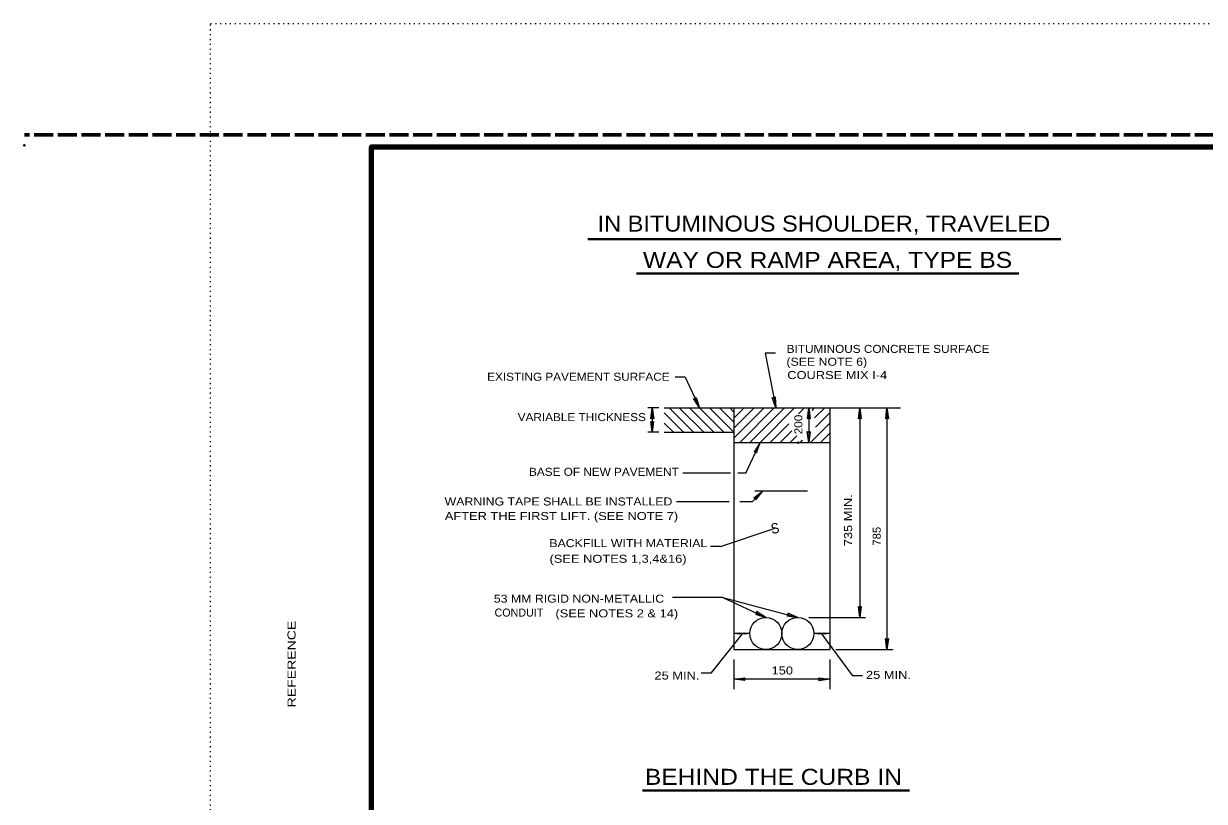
# Model space of a CAD drawing. Extents: x 312583 to 312854, y 144419 to 144597.
# Drawn here: x 312583.5 to 312695.6, y 144522.9 to 144596.8 of the extents above; entities that cross this region are included whole.
import ezdxf
from ezdxf.enums import TextEntityAlignment as Align

# ---------------------------------------------------------------- set-up
doc = ezdxf.new("R2010")
doc.units = 0
doc.header["$LTSCALE"] = 0.3
doc.header["$PDMODE"] = 32
doc.header["$PDSIZE"] = 0.15
doc.linetypes.add('DOTTED', pattern=[1.5, 0.3, -1.2])
doc.linetypes.add('LONG_DASHED', pattern=[7.5, 6, -1.5])
for name, color, linetype, lineweight in [('1', 7, 'Continuous', 13), ('62', 7, 'DOTTED', 13), ('63', 7, 'LONG_DASHED', 60)]:
    doc.layers.add(name, color=color, linetype=linetype, lineweight=lineweight)

msp = doc.modelspace()

# ---------------------------------------------------------------- linework, layer by layer
at = {"layer": '1', "lineweight": 40}
for p, q in [((312637.0349, 144576.3049), (312681.9618, 144576.3049)), ((312641.6591, 144573.0677), (312677.9712, 144573.0677)), ((312642.2278, 144523.9644), (312667.5907, 144523.9644))]:
    msp.add_line(p, q, dxfattribs=at)
at = {"layer": '1'}
for p, q in [((312646.2857, 144563.1996), (312645.335, 144563.1996)), ((312646.2857, 144563.1996), (312647.6427, 144560.2939)), ((312643.771, 144560.2939), (312642.7514, 144560.2939)), ((312643.1577, 144560.2939), (312643.1577, 144557.9786)), ((312646.1247, 144557.9786), (312644.2847, 144559.8186)), ((312647.083, 144557.9786), (312644.7677, 144560.2939)), ((312648.0414, 144557.9786), (312645.726, 144560.2939)), ((312648.9997, 144557.9786), (312646.6844, 144560.2939)), ((312649.958, 144557.9786), (312647.6427, 144560.2939)), ((312650.9164, 144557.9786), (312648.601, 144560.2939)), ((312650.9164, 144558.9369), (312649.5594, 144560.2939)), ((312650.9164, 144559.8953), (312650.5177, 144560.2939)), ((312650.9164, 144557.4189), (312653.7914, 144560.2939)), ((312650.9164, 144558.3773), (312652.833, 144560.2939)), ((312650.9164, 144559.3356), (312651.8747, 144560.2939)), ((312651.476, 144557.0203), (312654.7497, 144560.2939)), ((312652.4344, 144557.0203), (312655.708, 144560.2939)), ((312653.3927, 144557.0203), (312656.6664, 144560.2939)), ((312657.0497, 144559.7266), (312657.6247, 144560.2939)), ((312658.0234, 144560.2939), (312658.0234, 144557.0203)), ((312658.33, 144560.0486), (312658.583, 144560.2939)), ((312658.583, 144559.3433), (312659.5414, 144560.2939)), ((312658.6597, 144558.4616), (312660.0244, 144559.8186)), ((312662.8687, 144560.2939), (312662.8687, 144540.3913)), ((312665.4524, 144560.2939), (312665.4524, 144537.3553)), ((312645.1664, 144557.9786), (312644.2847, 144558.8603)), ((312654.351, 144557.0203), (312656.1144, 144558.7836)), ((312658.1844, 144557.0203), (312660.0244, 144558.8603)), ((312643.771, 144557.9786), (312642.7514, 144557.9786)), ((312655.3094, 144557.0203), (312656.421, 144558.1319)), ((312656.2677, 144557.0203), (312656.904, 144557.6566)), ((312657.226, 144557.0203), (312657.433, 144557.2273)), ((312659.1427, 144557.0203), (312660.0244, 144557.9019)), ((312652.0357, 144554.1146), (312653.3927, 144557.0203)), ((312650.5944, 144554.1146), (312646.071, 144554.1146)), ((312652.0357, 144554.1146), (312651.292, 144554.1146)), ((312652.649, 144551.3929), (312653.684, 144552.4279)), ((312650.4564, 144551.3929), (312645.4654, 144551.3929)), ((312652.649, 144551.3929), (312651.476, 144551.3929)), ((312649.6284, 144547.1303), (312654.7267, 144548.8553)), ((312649.6284, 144547.1303), (312648.6777, 144547.1303)), ((312649.8507, 144542.2926), (312645.082, 144542.2926)), ((312649.8507, 144542.2926), (312653.9524, 144540.3913)), ((312649.8507, 144542.2926), (312656.9884, 144540.3913)), ((312658.0234, 144540.3913), (312663.3977, 144540.3913)), ((312648.7467, 144535.1166), (312651.7214, 144538.8579)), ((312652.4344, 144538.8733), (312650.9164, 144538.8733)), ((312660.0244, 144538.8733), (312658.5064, 144538.8733)), ((312659.227, 144538.8579), (312662.1787, 144534.8559)), ((312660.5994, 144537.3553), (312666.0197, 144537.3553)), ((312650.9164, 144536.3969), (312650.9164, 144533.5756)), ((312660.0244, 144536.3969), (312660.0244, 144533.5756)), ((312648.7467, 144535.1166), (312647.796, 144535.1166)), ((312663.137, 144534.8559), (312662.1787, 144534.8559)), ((312660.0244, 144534.5339), (312650.9164, 144534.5339))]:
    msp.add_line(p, q, dxfattribs=at)
at = {"layer": '1', "lineweight": 25}
for p, q in [((312644.2847, 144560.2939), (312666.7404, 144560.2939)), ((312647.6427, 144560.2939), (312662.5007, 144560.2939)), ((312650.9164, 144560.2939), (312650.9164, 144537.3553)), ((312660.0244, 144560.2939), (312660.0244, 144537.3553)), ((312644.2847, 144557.9786), (312650.9164, 144557.9786)), ((312650.9164, 144557.0203), (312660.0244, 144557.0203)), ((312652.8944, 144552.4279), (312657.893, 144552.4279)), ((312650.9164, 144537.3553), (312660.0244, 144537.3553))]:
    msp.add_line(p, q, dxfattribs=at)
at = {"layer": '1', "lineweight": 158}
msp.add_lwpolyline([(312616.5, 144423.1446), (312616.5, 144585.0846), (312849, 144585.0846)], dxfattribs=at)
at = {"layer": '1'}
msp.add_lwpolyline([(312654.8494, 144565.4843), (312653.891, 144565.4843), (312654.8954, 144560.2939)], dxfattribs=at)
for points in [[(312647.3207, 144561.2829), (312647.6427, 144560.2939), (312647.0754, 144561.1756), (312647.244, 144561.1373)], [(312654.8187, 144561.3366), (312654.8954, 144560.2939), (312654.558, 144561.2829), (312654.719, 144561.2063)], [(312643.035, 144559.2589), (312643.1577, 144560.2939), (312643.2957, 144559.2589), (312643.1577, 144559.3586)], [(312657.9007, 144559.2589), (312658.0234, 144560.2939), (312658.1614, 144559.2589), (312658.0234, 144559.3586)], [(312662.746, 144559.2589), (312662.8687, 144560.2939), (312663.0067, 144559.2589), (312662.8687, 144559.3586)], [(312665.3297, 144559.2589), (312665.4524, 144560.2939), (312665.5904, 144559.2589), (312665.4524, 144559.3586)], [(312643.288, 144559.0136), (312643.1577, 144557.9786), (312643.0197, 144559.0136), (312643.1577, 144558.9139)], [(312658.1537, 144558.0553), (312658.0234, 144557.0203), (312657.8854, 144558.0553), (312658.0234, 144557.9556)], [(312653.0707, 144556.0313), (312653.3927, 144557.0203), (312652.8254, 144556.1386), (312652.994, 144556.1769)], [(312652.9864, 144551.5539), (312653.6304, 144552.3743), (312652.8024, 144551.7379), (312652.971, 144551.7149)], [(312652.9557, 144540.7133), (312653.9524, 144540.3913), (312653.0707, 144540.9509), (312653.1014, 144540.7823)], [(312655.9534, 144540.5446), (312656.9884, 144540.3913), (312656.0224, 144540.7976), (312656.0837, 144540.6366)], [(312662.999, 144541.4263), (312662.8687, 144540.3913), (312662.7307, 144541.4263), (312662.8687, 144541.3266)], [(312651.4914, 144538.8043), (312650.9164, 144538.8733), (312651.4914, 144538.9499), (312651.4377, 144538.8733)], [(312651.8517, 144538.9423), (312652.4344, 144538.8733), (312651.8517, 144538.7966), (312651.9054, 144538.8733)], [(312659.0814, 144538.8043), (312658.5064, 144538.8733), (312659.0814, 144538.9499), (312659.0277, 144538.8733)], [(312659.4417, 144538.9423), (312660.0244, 144538.8733), (312659.4417, 144538.7966), (312659.4954, 144538.8733)], [(312665.5827, 144538.3903), (312665.4524, 144537.3553), (312665.3144, 144538.3903), (312665.4524, 144538.2906)], [(312651.9514, 144534.4113), (312650.9164, 144534.5339), (312651.9514, 144534.6719), (312651.844, 144534.5339)], [(312658.9894, 144534.6643), (312660.0244, 144534.5339), (312658.9894, 144534.3959), (312659.089, 144534.5339)]]:
    msp.add_lwpolyline(points, close=True, dxfattribs=at)
at = {"layer": '1', "lineweight": 25}
for centre in [(312653.9485, 144538.8752), (312656.9845, 144538.8752)]:
    msp.add_circle(centre, 1.518, dxfattribs=at)
at = {"layer": '1'}
for p in [(312583.526, 144585.2246), (312657.019, 144557.0049)]:
    msp.add_point(p, dxfattribs=at)
at = {"layer": '62'}
for p, q in [((312601.2, 144596.7846), (312853.5, 144596.7846)), ((312601.2, 144418.5846), (312601.2, 144596.7846))]:
    msp.add_line(p, q, dxfattribs=at)
at = {"layer": '63'}
msp.add_line((312851.75, 144586.2246), (312583.526, 144586.2246), dxfattribs=at)

# ---------------------------------------------------------------- texts
at = {"layer": '1'}
for s, width, p in [('IN BITUMINOUS SHOULDER, TRAVELED', 1.1, (312659.4609, 144577.0343)), ('WAY OR RAMP AREA, TYPE BS', 1.15, (312659.8064, 144573.5937)), ('BEHIND THE CURB IN', 1.15, (312654.6636, 144524.5058))]:
    msp.add_text(s, height=1.52, dxfattribs=dict(at, width=width)).set_placement(p, align=Align.CENTER)
for s, width, p in [('BITUMINOUS CONCRETE SURFACE', 1.1, (312655.9284, 144565.5196)), ('(SEE NOTE 6)', 1.15, (312655.9025, 144564.3001)), ('EXISTING PAVEMENT SURFACE', 1.1, (312627.4758, 144562.8753)), ('COURSE MIX I-4', 1.2, (312655.982, 144563.0346)), ('VARIABLE THICKNESS', 1.1, (312630.3772, 144559.0413)), ('BASE OF NEW PAVEMENT', 1.1, (312631.4532, 144553.8462)), ('WARNING TAPE SHALL BE INSTALLED', 1.15, (312623.4381, 144551.0303)), ('AFTER THE FIRST LIFT. (SEE NOTE 7)', 1.2, (312623.457, 144549.6525)), ('BACKFILL WITH MATERIAL', 1.15, (312633.3832, 144547.0736)), ('(SEE NOTES 1,3,4&16)', 1.2, (312633.4017, 144545.5909)), ('53 MM RIGID NON-METALLIC', 1.15, (312628.1116, 144541.8051)), ('(SEE NOTES 2 & 14)', 1.2, (312633.9607, 144540.4066)), ('25 MIN.', 1.2, (312643.3684, 144534.5041)), ('150 ', 1.2, (312654.49, 144534.9839)), ('25 MIN.', 1.2, (312663.4584, 144534.5701))]:
    msp.add_text(s, height=0.76, dxfattribs=dict(at, width=width)).set_placement(p)
for s, height, width, p in [('200', 0.76, 1.1, (312657.4158, 144557.7882)), ('735 MIN.', 0.76, 1.2, (312662.1419, 144547.1572)), ('785', 0.76, 1.05, (312664.8569, 144547.2207)), ('REFERENCE                                                              ', 0.7682, 1.3, (312609.2854, 144531.8549))]:
    msp.add_text(s, height=height, rotation=90, dxfattribs=dict(at, width=width)).set_placement(p)
at = {"layer": '1', "width": 0.9}
msp.add_text('S', height=0.9804, rotation=10, dxfattribs=at).set_placement((312654.8995, 144548.3856), align=Align.CENTER)
at = {"layer": '1'}
msp.add_text('CONDUIT', height=0.76, dxfattribs=at).set_placement((312628.1809, 144540.4834))

doc.saveas('drawing.dxf')
